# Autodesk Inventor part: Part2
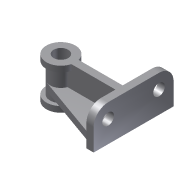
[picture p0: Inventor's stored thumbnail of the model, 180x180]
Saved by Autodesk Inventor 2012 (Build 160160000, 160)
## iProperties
Shininess: 77.0
Length Units: 11269
Angle Units: 11279
Time Units: 11290
Mass Units: 11283
Length Display Precision: 3
Angle Display Precision: 2
Created: 2001-12
Part Number: Part2
Document SubType Name: Modeling
Density: 1 g/cm^3
Material: Default
Density: 0.0
Volumn: 0.0
Area: 0.0
PropertySet Name: Model Information
Control State: 0
Master: False
Checked Out: False
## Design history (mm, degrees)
sketch "Sketch1"
  geometry: L1 (67.049, 55)-(67.049, -55); L2 (60.402, -45.579)-(-27.979, -14.132); L3 (-27.979, 14.132)-(60.402, 45.579); A1 r 10 centre (57.049, -55) between (67.049, -55) and (60.402, -45.579); A2 r 15 centre (-22.951, 0) between (-27.979, 14.132) and (-27.979, -14.132); A3 r 10 centre (57.049, 55) between (60.402, 45.579) and (67.049, 55)
  constraints: 6 end point, 6 point on circle, 6 tangent, 3 centre point, 1 equal length, 1 equal radius, 1 vertical
  dimensions: "d0" = 15 radius of A2; "d1" = 10 radius of A1; "d2" = 90 distance from line of L1 A2.centre; "d3" = 110 distance of L1.start L1.end
extrude "Extrusion1" new body sketch "Sketch1" distance "d4" = 10; taper "d5" = 0 deg
sketch "Sketch2"
  geometry: L1 (0, 110)-(0, 0) reference; L2 (0, 0)-(-30, 0); L3 (-50, 20)-(-50, 90); L4 (-30, 110)-(0, 110); C1 r 8 at (-30, 90); C2 r 8 at (-30, 20); A1 r 20 centre (-30, 20) between (-50, 20) and (-30, 0); A2 r 20 centre (-30, 90) between (-30, 110) and (-50, 90)
  constraints: 6 end point, 4 centre point, 4 point on circle, 4 tangent, 3 perpendicular, 2 coincident, 1 equal radius, 1 parallel
  dimensions: "d6" = 20 radius of A2; "d7" = 50 distance between parallel lines of L1 L3; "d10" = 16 diameter of C1
extrude "Extrusion2" join sketch "Sketch2" distance "d8" = 10; taper "d9" = 0 deg
workplane "Work Plane1"
sketch "Sketch3"
  geometry: C1 r 15 at (-22.951, 0); A1 r 15 centre (-22.951, 0) between (-27.979, 14.132) and (-27.979, -14.132) reference
  constraints: 2 concentric, 1 centre point
extrude "Extrusion3" join sketch "Sketch3" distance "d12" = 56; taper "d13" = 0 deg
sketch "Sketch4"
  geometry: L1 (7.951, 40)-(-57.058, 40); L2 (7.951, 40)-(37.951, 40) reference; L3 (-67.049, 50)-(-67.049, 30) reference; L4 (-77.049, 0)-(-77.049, 30) reference; L5 (-67.049, 0)-(-77.049, 0) reference; A1 r 10 centre (-57.058, 50) between (-67.049, 49.599) and (-57.058, 40)
  constraints: 2 end point, 2 point on circle, 2 point on line, 1 centre point, 1 horizontal, 1 tangent
  dimensions: "d14" = 85 distance from line of L4 L1.start; "d15" = 50 distance from line of L5 A1.centre
feature "Rib1" sketch "Sketch4" dims "d16" = 1, "d17" = 10
sketch "Sketch5"
  geometry: C1 r 20 at (-22.951, 0); 1 further point
  constraints: 1 centre point, 1 coincident
  dimensions: "d18" = 40 diameter of C1
extrude "Extrusion4" join sketch "Sketch5" distance "d19" = 8; taper "d20" = 0 deg
workplane "Work Plane2"
mirror "Mirror1"
sketch "Sketch6"
  geometry: A1 r 20 centre (-22.951, 0) between (-3.586, 5) and (-3.586, -5) reference
hole "Hole1" sketch "Sketch6" at (-22.951, 0) diameter "d22" = 20; stored, may be unused: countersink angle "d26" = 82 deg, drill point angle "d28" = 118 deg; dims "d23" = 6, "d24" = 4, "d25" = 2, "d27" = 8
body "Solid1"
other parameters: "d21" = -28
